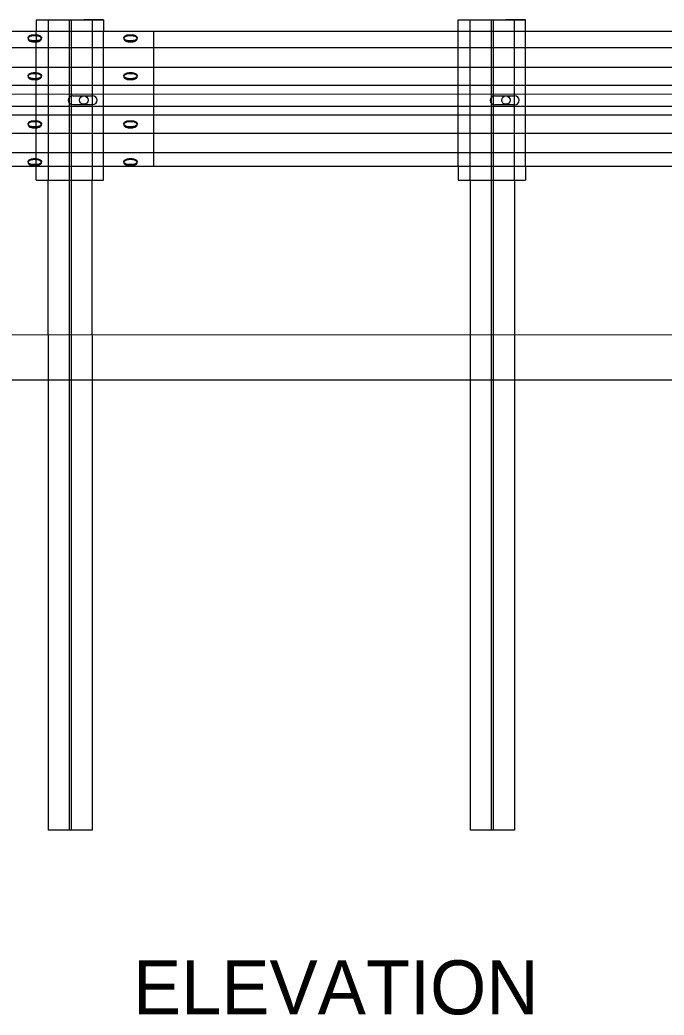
# Model space of a CAD drawing. Extents: x 49991 to 50160, y 49948 to 50051.
# Drawn here: x 50005.602 to 50006.556, y 49994.044 to 49995.518 of the extents above; entities that cross this region are included whole.
import ezdxf

# ---------------------------------------------------------------- set-up
doc = ezdxf.new("R2010")
doc.units = 0
for name, color, linetype in [('Level 1', 7, 'Continuous'), ('Level 2', 7, 'Continuous'), ('Level 4', 7, 'Continuous')]:
    doc.layers.add(name, color=color, linetype=linetype)

msp = doc.modelspace()

# ---------------------------------------------------------------- linework, layer by layer
at = {"layer": 'Level 1'}
for p, q in [((50005.6258, 49995.5184), (50005.7258, 49995.5184)), ((50005.6258, 49995.5184), (50005.6258, 49995.5019)), ((50005.6435, 49995.5184), (50005.7091, 49995.5184)), ((50005.7258, 49995.5184), (50005.6966, 49995.5184)), ((50005.7258, 49995.5184), (50005.7258, 49995.5019)), ((50006.2508, 49995.5184), (50006.3508, 49995.5184)), ((50006.2508, 49995.5019), (50006.2508, 49995.5184)), ((50006.2685, 49995.5184), (50006.3341, 49995.5184)), ((50006.3508, 49995.5184), (50006.3216, 49995.5184)), ((50006.3508, 49995.5018), (50006.3508, 49995.5184)), ((50004.3866, 49995.502), (50011.6716, 49995.5015)), ((50005.6219, 49995.4963), (50005.6258, 49995.4963)), ((50005.6219, 49995.4949), (50005.6219, 49995.4963)), ((50005.6258, 49995.4949), (50005.6219, 49995.4949)), ((50005.6258, 49995.4949), (50005.6258, 49995.4963)), ((50005.6258, 49995.4949), (50005.6258, 49995.4875)), ((50005.7636, 49995.4949), (50005.7636, 49995.4963)), ((50005.7636, 49995.4963), (50005.7675, 49995.4963)), ((50005.7675, 49995.4949), (50005.7636, 49995.4949)), ((50005.7675, 49995.4949), (50005.7675, 49995.4963)), ((50005.614, 49995.4919), (50005.614, 49995.4905)), ((50005.6258, 49995.4875), (50005.6219, 49995.4875)), ((50005.6219, 49995.4861), (50005.6219, 49995.4875)), ((50005.6219, 49995.4861), (50005.6258, 49995.4861)), ((50005.6258, 49995.4861), (50005.6258, 49995.4875)), ((50005.6337, 49995.4905), (50005.6337, 49995.4919)), ((50005.7675, 49995.4875), (50005.7636, 49995.4875)), ((50005.7636, 49995.4861), (50005.7636, 49995.4875)), ((50005.7636, 49995.4861), (50005.7675, 49995.4861)), ((50005.7675, 49995.4861), (50005.7675, 49995.4875)), ((50005.7754, 49995.4905), (50005.7754, 49995.4919)), ((50004.5497, 49995.4777), (50011.6716, 49995.4777)), ((50004.5497, 49995.4486), (50011.6716, 49995.448)), ((50005.614, 49995.4358), (50005.614, 49995.4344)), ((50005.6219, 49995.4403), (50005.6258, 49995.4403)), ((50005.6219, 49995.4403), (50005.6219, 49995.4388)), ((50005.6258, 49995.4388), (50005.6219, 49995.4388)), ((50005.6258, 49995.4403), (50005.6258, 49995.4388)), ((50005.6258, 49995.4314), (50005.6258, 49995.4388)), ((50005.6337, 49995.4344), (50005.6337, 49995.4358)), ((50005.7636, 49995.4403), (50005.7675, 49995.4403)), ((50005.7636, 49995.4403), (50005.7636, 49995.4388)), ((50005.7675, 49995.4388), (50005.7636, 49995.4388)), ((50005.7675, 49995.4403), (50005.7675, 49995.4388)), ((50005.7754, 49995.4344), (50005.7754, 49995.4358)), ((50004.5497, 49995.4215), (50011.6716, 49995.4225)), ((50005.6219, 49995.4314), (50005.6219, 49995.43)), ((50005.6258, 49995.4314), (50005.6219, 49995.4314)), ((50005.6219, 49995.43), (50005.6258, 49995.43)), ((50005.6258, 49995.4314), (50005.6258, 49995.43)), ((50005.7636, 49995.4314), (50005.7636, 49995.43)), ((50005.7675, 49995.4314), (50005.7636, 49995.4314)), ((50005.7636, 49995.43), (50005.7675, 49995.43)), ((50005.7675, 49995.4314), (50005.7675, 49995.43)), ((50005.0854, 49995.409), (50011.6716, 49995.4068)), ((50005.68, 49995.4061), (50005.7095, 49995.4061)), ((50006.3049, 49995.406), (50006.3345, 49995.406)), ((50011.6716, 49995.3902), (50005.5897, 49995.3903)), ((50005.7095, 49995.3929), (50005.68, 49995.3929)), ((50006.3345, 49995.3929), (50006.3049, 49995.3929)), ((50011.6716, 49995.3773), (50005.5897, 49995.3773)), ((50005.614, 49995.3646), (50005.614, 49995.3632)), ((50005.6219, 49995.369), (50005.6258, 49995.369)), ((50005.6219, 49995.3676), (50005.6219, 49995.369)), ((50005.6258, 49995.3676), (50005.6219, 49995.3676)), ((50005.6258, 49995.3676), (50005.6258, 49995.369)), ((50005.6258, 49995.3602), (50005.6258, 49995.3676)), ((50005.6337, 49995.3632), (50005.6337, 49995.3646)), ((50005.7636, 49995.369), (50005.7675, 49995.369)), ((50005.7636, 49995.3676), (50005.7636, 49995.369)), ((50005.7675, 49995.3676), (50005.7636, 49995.3676)), ((50005.7675, 49995.3676), (50005.7675, 49995.369)), ((50005.7754, 49995.3632), (50005.7754, 49995.3646)), ((50011.6716, 49995.3504), (50005.5897, 49995.3504)), ((50005.6258, 49995.3602), (50005.6219, 49995.3602)), ((50005.6219, 49995.3588), (50005.6219, 49995.3602)), ((50005.6219, 49995.3588), (50005.6258, 49995.3588)), ((50005.6258, 49995.3588), (50005.6258, 49995.3602)), ((50005.7675, 49995.3602), (50005.7636, 49995.3602)), ((50005.7636, 49995.3588), (50005.7636, 49995.3602)), ((50005.7636, 49995.3588), (50005.7675, 49995.3588)), ((50005.7675, 49995.3588), (50005.7675, 49995.3602)), ((50011.6716, 49995.3214), (50005.5897, 49995.3214)), ((50005.614, 49995.3085), (50005.614, 49995.3071)), ((50005.6219, 49995.313), (50005.6258, 49995.313)), ((50005.6219, 49995.313), (50005.6219, 49995.3115)), ((50005.6258, 49995.3115), (50005.6219, 49995.3115)), ((50005.6219, 49995.3041), (50005.6219, 49995.3027)), ((50005.6258, 49995.3041), (50005.6219, 49995.3041)), ((50005.6219, 49995.3027), (50005.6258, 49995.3027)), ((50005.6258, 49995.313), (50005.6258, 49995.3115)), ((50005.6258, 49995.3041), (50005.6258, 49995.3115)), ((50005.6258, 49995.3041), (50005.6258, 49995.3027)), ((50005.6337, 49995.3071), (50005.6337, 49995.3085)), ((50005.7636, 49995.313), (50005.7675, 49995.313)), ((50005.7636, 49995.313), (50005.7636, 49995.3115)), ((50005.7675, 49995.3115), (50005.7636, 49995.3115)), ((50005.7636, 49995.3041), (50005.7636, 49995.3027)), ((50005.7675, 49995.3041), (50005.7636, 49995.3041)), ((50005.7636, 49995.3027), (50005.7675, 49995.3027)), ((50005.7675, 49995.313), (50005.7675, 49995.3115)), ((50005.7675, 49995.3041), (50005.7675, 49995.3027)), ((50005.7754, 49995.3071), (50005.7754, 49995.3085)), ((50011.6716, 49995.3012), (50005.5897, 49995.3012)), ((50005.6258, 49995.2809), (50005.6258, 49995.3012)), ((50005.7258, 49995.2809), (50005.7258, 49995.3012)), ((50006.2508, 49995.3012), (50006.2508, 49995.2809)), ((50006.3508, 49995.3012), (50006.3508, 49995.2809)), ((50005.6258, 49995.2809), (50005.7258, 49995.2809)), ((50005.6435, 49995.0518), (50005.6435, 49995.2809)), ((50005.7091, 49995.0518), (50005.7091, 49995.2809)), ((50006.2508, 49995.2809), (50006.3508, 49995.2809)), ((50006.2685, 49995.2809), (50006.2685, 49995.0518)), ((50006.3341, 49995.2809), (50006.3341, 49995.0517)), ((50011.6716, 49995.0515), (50000.8175, 49995.052)), ((49999.8238, 49994.9854), (50011.6716, 49994.9849))]:
    msp.add_line(p, q, dxfattribs=at)
for points in [[(50005.6219, 49995.4875), (50005.6205, 49995.4876), (50005.6192, 49995.4878), (50005.6179, 49995.4881), (50005.6168, 49995.4885), (50005.6158, 49995.4891), (50005.6151, 49995.4897), (50005.6145, 49995.4904), (50005.6141, 49995.4912), (50005.614, 49995.4919), (50005.6141, 49995.4927), (50005.6145, 49995.4934), (50005.6151, 49995.4941), (50005.6158, 49995.4948), (50005.6168, 49995.4953), (50005.6179, 49995.4957), (50005.6192, 49995.4961), (50005.6205, 49995.4963), (50005.6219, 49995.4963)], [(50005.6219, 49995.4949), (50005.6205, 49995.4948), (50005.6192, 49995.4946), (50005.6179, 49995.4943), (50005.6168, 49995.4938), (50005.6158, 49995.4933), (50005.6151, 49995.4927), (50005.6145, 49995.492), (50005.6141, 49995.4912), (50005.6141, 49995.4912)], [(50005.6258, 49995.4963), (50005.6272, 49995.4963), (50005.6285, 49995.4961), (50005.6298, 49995.4957), (50005.6309, 49995.4953), (50005.6318, 49995.4948), (50005.6326, 49995.4941), (50005.6332, 49995.4934), (50005.6336, 49995.4927), (50005.6337, 49995.4919), (50005.6336, 49995.4912), (50005.6332, 49995.4904), (50005.6326, 49995.4897), (50005.6318, 49995.4891), (50005.6309, 49995.4885), (50005.6298, 49995.4881), (50005.6285, 49995.4878), (50005.6272, 49995.4876), (50005.6258, 49995.4875)], [(50005.6336, 49995.4912), (50005.6336, 49995.4912), (50005.6332, 49995.492), (50005.6326, 49995.4927), (50005.6318, 49995.4933), (50005.6309, 49995.4938), (50005.6298, 49995.4943), (50005.6285, 49995.4946), (50005.6272, 49995.4948), (50005.6258, 49995.4949)], [(50005.7636, 49995.4875), (50005.7622, 49995.4876), (50005.7609, 49995.4878), (50005.7597, 49995.4881), (50005.7586, 49995.4885), (50005.7576, 49995.4891), (50005.7568, 49995.4897), (50005.7562, 49995.4904), (50005.7559, 49995.4912), (50005.7557, 49995.4919), (50005.7559, 49995.4927), (50005.7562, 49995.4934), (50005.7568, 49995.4941), (50005.7576, 49995.4948), (50005.7586, 49995.4953), (50005.7597, 49995.4957), (50005.7609, 49995.4961), (50005.7622, 49995.4963), (50005.7636, 49995.4963)], [(50005.7636, 49995.4949), (50005.7622, 49995.4948), (50005.7609, 49995.4946), (50005.7597, 49995.4943), (50005.7586, 49995.4938), (50005.7576, 49995.4933), (50005.7568, 49995.4927), (50005.7562, 49995.492), (50005.7559, 49995.4912), (50005.7558, 49995.4912)], [(50005.7675, 49995.4963), (50005.7689, 49995.4963), (50005.7702, 49995.4961), (50005.7715, 49995.4957), (50005.7726, 49995.4953), (50005.7736, 49995.4948), (50005.7744, 49995.4941), (50005.7749, 49995.4934), (50005.7753, 49995.4927), (50005.7754, 49995.4919), (50005.7753, 49995.4912), (50005.7749, 49995.4904), (50005.7744, 49995.4897), (50005.7736, 49995.4891), (50005.7726, 49995.4885), (50005.7715, 49995.4881), (50005.7702, 49995.4878), (50005.7689, 49995.4876), (50005.7675, 49995.4875)], [(50005.7753, 49995.4912), (50005.7753, 49995.4912), (50005.7749, 49995.492), (50005.7744, 49995.4927), (50005.7736, 49995.4933), (50005.7726, 49995.4938), (50005.7715, 49995.4943), (50005.7702, 49995.4946), (50005.7689, 49995.4948), (50005.7675, 49995.4949)], [(50005.6141, 49995.4912), (50005.614, 49995.4905), (50005.6141, 49995.4897), (50005.6145, 49995.489), (50005.6151, 49995.4883), (50005.6158, 49995.4876), (50005.6168, 49995.4871), (50005.6179, 49995.4867), (50005.6192, 49995.4863), (50005.6205, 49995.4861), (50005.6219, 49995.4861)], [(50005.6258, 49995.4861), (50005.6272, 49995.4861), (50005.6285, 49995.4863), (50005.6298, 49995.4867), (50005.6309, 49995.4871), (50005.6318, 49995.4876), (50005.6326, 49995.4883), (50005.6332, 49995.489), (50005.6336, 49995.4897), (50005.6337, 49995.4905), (50005.6336, 49995.4912)], [(50005.7558, 49995.4912), (50005.7557, 49995.4905), (50005.7559, 49995.4897), (50005.7562, 49995.489), (50005.7568, 49995.4883), (50005.7576, 49995.4876), (50005.7586, 49995.4871), (50005.7597, 49995.4867), (50005.7609, 49995.4863), (50005.7622, 49995.4861), (50005.7636, 49995.4861)], [(50005.7675, 49995.4861), (50005.7689, 49995.4861), (50005.7702, 49995.4863), (50005.7715, 49995.4867), (50005.7726, 49995.4871), (50005.7736, 49995.4876), (50005.7744, 49995.4883), (50005.7749, 49995.489), (50005.7753, 49995.4897), (50005.7754, 49995.4905), (50005.7753, 49995.4912)], [(50005.6141, 49995.4351), (50005.614, 49995.4358), (50005.6141, 49995.4366), (50005.6145, 49995.4374), (50005.6151, 49995.438), (50005.6158, 49995.4387), (50005.6168, 49995.4392), (50005.6179, 49995.4397), (50005.6192, 49995.44), (50005.6205, 49995.4402), (50005.6219, 49995.4403)], [(50005.6219, 49995.4388), (50005.6205, 49995.4387), (50005.6192, 49995.4385), (50005.6179, 49995.4382), (50005.6168, 49995.4378), (50005.6158, 49995.4372), (50005.6151, 49995.4366), (50005.6145, 49995.4359), (50005.6141, 49995.4352), (50005.614, 49995.4344), (50005.6141, 49995.4336), (50005.6145, 49995.4329), (50005.6151, 49995.4322), (50005.6158, 49995.4316), (50005.6168, 49995.431), (50005.6179, 49995.4306), (50005.6192, 49995.4302), (50005.6205, 49995.43), (50005.6219, 49995.43)], [(50005.6219, 49995.4314), (50005.6205, 49995.4315), (50005.6192, 49995.4317), (50005.6179, 49995.432), (50005.6168, 49995.4325), (50005.6158, 49995.433), (50005.6151, 49995.4336), (50005.6145, 49995.4343), (50005.6141, 49995.4351), (50005.6141, 49995.4351)], [(50005.6258, 49995.4403), (50005.6272, 49995.4402), (50005.6285, 49995.44), (50005.6298, 49995.4397), (50005.6309, 49995.4392), (50005.6318, 49995.4387), (50005.6326, 49995.438), (50005.6332, 49995.4374), (50005.6336, 49995.4366), (50005.6337, 49995.4358), (50005.6336, 49995.4351)], [(50005.6258, 49995.43), (50005.6272, 49995.43), (50005.6285, 49995.4302), (50005.6298, 49995.4306), (50005.6309, 49995.431), (50005.6318, 49995.4316), (50005.6326, 49995.4322), (50005.6332, 49995.4329), (50005.6336, 49995.4336), (50005.6337, 49995.4344), (50005.6336, 49995.4352), (50005.6332, 49995.4359), (50005.6326, 49995.4366), (50005.6318, 49995.4372), (50005.6309, 49995.4378), (50005.6298, 49995.4382), (50005.6285, 49995.4385), (50005.6272, 49995.4387), (50005.6258, 49995.4388)], [(50005.6336, 49995.4351), (50005.6336, 49995.4351), (50005.6332, 49995.4343), (50005.6326, 49995.4336), (50005.6318, 49995.433), (50005.6309, 49995.4325), (50005.6298, 49995.432), (50005.6285, 49995.4317), (50005.6272, 49995.4315), (50005.6258, 49995.4314)], [(50005.7558, 49995.4351), (50005.7557, 49995.4358), (50005.7559, 49995.4366), (50005.7562, 49995.4374), (50005.7568, 49995.438), (50005.7576, 49995.4387), (50005.7586, 49995.4392), (50005.7597, 49995.4397), (50005.7609, 49995.44), (50005.7622, 49995.4402), (50005.7636, 49995.4403)], [(50005.7636, 49995.4388), (50005.7622, 49995.4387), (50005.7609, 49995.4385), (50005.7597, 49995.4382), (50005.7586, 49995.4378), (50005.7576, 49995.4372), (50005.7568, 49995.4366), (50005.7562, 49995.4359), (50005.7559, 49995.4352), (50005.7557, 49995.4344), (50005.7559, 49995.4336), (50005.7562, 49995.4329), (50005.7568, 49995.4322), (50005.7576, 49995.4316), (50005.7586, 49995.431), (50005.7597, 49995.4306), (50005.7609, 49995.4302), (50005.7622, 49995.43), (50005.7636, 49995.43)], [(50005.7636, 49995.4314), (50005.7622, 49995.4315), (50005.7609, 49995.4317), (50005.7597, 49995.432), (50005.7586, 49995.4325), (50005.7576, 49995.433), (50005.7568, 49995.4336), (50005.7562, 49995.4343), (50005.7559, 49995.4351), (50005.7558, 49995.4351)], [(50005.7675, 49995.4403), (50005.7689, 49995.4402), (50005.7702, 49995.44), (50005.7715, 49995.4397), (50005.7726, 49995.4392), (50005.7736, 49995.4387), (50005.7744, 49995.438), (50005.7749, 49995.4374), (50005.7753, 49995.4366), (50005.7754, 49995.4358), (50005.7753, 49995.4351)], [(50005.7675, 49995.43), (50005.7689, 49995.43), (50005.7702, 49995.4302), (50005.7715, 49995.4306), (50005.7726, 49995.431), (50005.7736, 49995.4316), (50005.7744, 49995.4322), (50005.7749, 49995.4329), (50005.7753, 49995.4336), (50005.7754, 49995.4344), (50005.7753, 49995.4352), (50005.7749, 49995.4359), (50005.7744, 49995.4366), (50005.7736, 49995.4372), (50005.7726, 49995.4378), (50005.7715, 49995.4382), (50005.7702, 49995.4385), (50005.7689, 49995.4387), (50005.7675, 49995.4388)], [(50005.7753, 49995.4351), (50005.7753, 49995.4351), (50005.7749, 49995.4343), (50005.7744, 49995.4336), (50005.7736, 49995.433), (50005.7726, 49995.4325), (50005.7715, 49995.432), (50005.7702, 49995.4317), (50005.7689, 49995.4315), (50005.7675, 49995.4314)], [(50005.6219, 49995.3602), (50005.6205, 49995.3603), (50005.6192, 49995.3605), (50005.6179, 49995.3608), (50005.6168, 49995.3612), (50005.6158, 49995.3618), (50005.6151, 49995.3624), (50005.6145, 49995.3631), (50005.6141, 49995.3639), (50005.614, 49995.3646), (50005.6141, 49995.3654), (50005.6145, 49995.3661), (50005.6151, 49995.3668), (50005.6158, 49995.3675), (50005.6168, 49995.368), (50005.6179, 49995.3684), (50005.6192, 49995.3688), (50005.6205, 49995.369), (50005.6219, 49995.369)], [(50005.6141, 49995.3639), (50005.614, 49995.3632), (50005.6141, 49995.3624), (50005.6145, 49995.3617), (50005.6151, 49995.361), (50005.6158, 49995.3603), (50005.6168, 49995.3598), (50005.6179, 49995.3594), (50005.6192, 49995.359), (50005.6205, 49995.3588), (50005.6219, 49995.3588)], [(50005.6219, 49995.3676), (50005.6205, 49995.3675), (50005.6192, 49995.3673), (50005.6179, 49995.367), (50005.6168, 49995.3666), (50005.6158, 49995.366), (50005.6151, 49995.3654), (50005.6145, 49995.3647), (50005.6141, 49995.3639), (50005.6141, 49995.3639)], [(50005.6258, 49995.369), (50005.6272, 49995.369), (50005.6285, 49995.3688), (50005.6298, 49995.3684), (50005.6309, 49995.368), (50005.6318, 49995.3675), (50005.6326, 49995.3668), (50005.6332, 49995.3661), (50005.6336, 49995.3654), (50005.6337, 49995.3646), (50005.6336, 49995.3639), (50005.6332, 49995.3631), (50005.6326, 49995.3624), (50005.6318, 49995.3618), (50005.6309, 49995.3612), (50005.6298, 49995.3608), (50005.6285, 49995.3605), (50005.6272, 49995.3603), (50005.6258, 49995.3602)], [(50005.6336, 49995.3639), (50005.6336, 49995.3639), (50005.6332, 49995.3647), (50005.6326, 49995.3654), (50005.6318, 49995.366), (50005.6309, 49995.3666), (50005.6298, 49995.367), (50005.6285, 49995.3673), (50005.6272, 49995.3675), (50005.6258, 49995.3676)], [(50005.6258, 49995.3588), (50005.6272, 49995.3588), (50005.6285, 49995.359), (50005.6298, 49995.3594), (50005.6309, 49995.3598), (50005.6318, 49995.3603), (50005.6326, 49995.361), (50005.6332, 49995.3617), (50005.6336, 49995.3624), (50005.6337, 49995.3632), (50005.6336, 49995.3639)], [(50005.7636, 49995.3602), (50005.7622, 49995.3603), (50005.7609, 49995.3605), (50005.7597, 49995.3608), (50005.7586, 49995.3612), (50005.7576, 49995.3618), (50005.7568, 49995.3624), (50005.7562, 49995.3631), (50005.7559, 49995.3639), (50005.7557, 49995.3646), (50005.7559, 49995.3654), (50005.7562, 49995.3661), (50005.7568, 49995.3668), (50005.7576, 49995.3675), (50005.7586, 49995.368), (50005.7597, 49995.3684), (50005.7609, 49995.3688), (50005.7622, 49995.369), (50005.7636, 49995.369)], [(50005.7558, 49995.3639), (50005.7557, 49995.3632), (50005.7559, 49995.3624), (50005.7562, 49995.3617), (50005.7568, 49995.361), (50005.7576, 49995.3603), (50005.7586, 49995.3598), (50005.7597, 49995.3594), (50005.7609, 49995.359), (50005.7622, 49995.3588), (50005.7636, 49995.3588)], [(50005.7636, 49995.3676), (50005.7622, 49995.3675), (50005.7609, 49995.3673), (50005.7597, 49995.367), (50005.7586, 49995.3666), (50005.7576, 49995.366), (50005.7568, 49995.3654), (50005.7562, 49995.3647), (50005.7559, 49995.3639), (50005.7558, 49995.3639)], [(50005.7675, 49995.369), (50005.7689, 49995.369), (50005.7702, 49995.3688), (50005.7715, 49995.3684), (50005.7726, 49995.368), (50005.7736, 49995.3675), (50005.7744, 49995.3668), (50005.7749, 49995.3661), (50005.7753, 49995.3654), (50005.7754, 49995.3646), (50005.7753, 49995.3639), (50005.7749, 49995.3631), (50005.7744, 49995.3624), (50005.7736, 49995.3618), (50005.7726, 49995.3612), (50005.7715, 49995.3608), (50005.7702, 49995.3605), (50005.7689, 49995.3603), (50005.7675, 49995.3602)], [(50005.7753, 49995.3639), (50005.7753, 49995.3639), (50005.7749, 49995.3647), (50005.7744, 49995.3654), (50005.7736, 49995.366), (50005.7726, 49995.3666), (50005.7715, 49995.367), (50005.7702, 49995.3673), (50005.7689, 49995.3675), (50005.7675, 49995.3676)], [(50005.7675, 49995.3588), (50005.7689, 49995.3588), (50005.7702, 49995.359), (50005.7715, 49995.3594), (50005.7726, 49995.3598), (50005.7736, 49995.3603), (50005.7744, 49995.361), (50005.7749, 49995.3617), (50005.7753, 49995.3624), (50005.7754, 49995.3632), (50005.7753, 49995.3639)], [(50005.6141, 49995.3078), (50005.614, 49995.3085), (50005.6141, 49995.3093), (50005.6145, 49995.3101), (50005.6151, 49995.3107), (50005.6158, 49995.3114), (50005.6168, 49995.3119), (50005.6179, 49995.3124), (50005.6192, 49995.3127), (50005.6205, 49995.3129), (50005.6219, 49995.313)], [(50005.6219, 49995.3115), (50005.6205, 49995.3114), (50005.6192, 49995.3112), (50005.6179, 49995.3109), (50005.6168, 49995.3105), (50005.6158, 49995.3099), (50005.6151, 49995.3093), (50005.6145, 49995.3086), (50005.6141, 49995.3079), (50005.614, 49995.3071), (50005.6141, 49995.3063), (50005.6145, 49995.3056), (50005.6151, 49995.3049), (50005.6158, 49995.3043), (50005.6168, 49995.3037), (50005.6179, 49995.3033), (50005.6192, 49995.303), (50005.6205, 49995.3028), (50005.6219, 49995.3027)], [(50005.6219, 49995.3041), (50005.6205, 49995.3042), (50005.6192, 49995.3044), (50005.6179, 49995.3047), (50005.6168, 49995.3052), (50005.6158, 49995.3057), (50005.6151, 49995.3063), (50005.6145, 49995.307), (50005.6141, 49995.3078), (50005.6141, 49995.3078)], [(50005.6258, 49995.313), (50005.6272, 49995.3129), (50005.6285, 49995.3127), (50005.6298, 49995.3124), (50005.6309, 49995.3119), (50005.6318, 49995.3114), (50005.6326, 49995.3107), (50005.6332, 49995.3101), (50005.6336, 49995.3093), (50005.6337, 49995.3085), (50005.6336, 49995.3078)], [(50005.6258, 49995.3027), (50005.6272, 49995.3028), (50005.6285, 49995.303), (50005.6298, 49995.3033), (50005.6309, 49995.3037), (50005.6318, 49995.3043), (50005.6326, 49995.3049), (50005.6332, 49995.3056), (50005.6336, 49995.3063), (50005.6337, 49995.3071), (50005.6336, 49995.3079), (50005.6332, 49995.3086), (50005.6326, 49995.3093), (50005.6318, 49995.3099), (50005.6309, 49995.3105), (50005.6298, 49995.3109), (50005.6285, 49995.3112), (50005.6272, 49995.3114), (50005.6258, 49995.3115)], [(50005.6336, 49995.3078), (50005.6336, 49995.3078), (50005.6332, 49995.307), (50005.6326, 49995.3063), (50005.6318, 49995.3057), (50005.6309, 49995.3052), (50005.6298, 49995.3047), (50005.6285, 49995.3044), (50005.6272, 49995.3042), (50005.6258, 49995.3041)], [(50005.7558, 49995.3078), (50005.7557, 49995.3085), (50005.7559, 49995.3093), (50005.7562, 49995.3101), (50005.7568, 49995.3107), (50005.7576, 49995.3114), (50005.7586, 49995.3119), (50005.7597, 49995.3124), (50005.7609, 49995.3127), (50005.7622, 49995.3129), (50005.7636, 49995.313)], [(50005.7636, 49995.3115), (50005.7622, 49995.3114), (50005.7609, 49995.3112), (50005.7597, 49995.3109), (50005.7586, 49995.3105), (50005.7576, 49995.3099), (50005.7568, 49995.3093), (50005.7562, 49995.3086), (50005.7559, 49995.3079), (50005.7557, 49995.3071), (50005.7559, 49995.3063), (50005.7562, 49995.3056), (50005.7568, 49995.3049), (50005.7576, 49995.3043), (50005.7586, 49995.3037), (50005.7597, 49995.3033), (50005.7609, 49995.303), (50005.7622, 49995.3028), (50005.7636, 49995.3027)], [(50005.7636, 49995.3041), (50005.7622, 49995.3042), (50005.7609, 49995.3044), (50005.7597, 49995.3047), (50005.7586, 49995.3052), (50005.7576, 49995.3057), (50005.7568, 49995.3063), (50005.7562, 49995.307), (50005.7559, 49995.3078), (50005.7558, 49995.3078)], [(50005.7675, 49995.313), (50005.7689, 49995.3129), (50005.7702, 49995.3127), (50005.7715, 49995.3124), (50005.7726, 49995.3119), (50005.7736, 49995.3114), (50005.7744, 49995.3107), (50005.7749, 49995.3101), (50005.7753, 49995.3093), (50005.7754, 49995.3085), (50005.7753, 49995.3078)], [(50005.7675, 49995.3027), (50005.7689, 49995.3028), (50005.7702, 49995.303), (50005.7715, 49995.3033), (50005.7726, 49995.3037), (50005.7736, 49995.3043), (50005.7744, 49995.3049), (50005.7749, 49995.3056), (50005.7753, 49995.3063), (50005.7754, 49995.3071), (50005.7753, 49995.3079), (50005.7749, 49995.3086), (50005.7744, 49995.3093), (50005.7736, 49995.3099), (50005.7726, 49995.3105), (50005.7715, 49995.3109), (50005.7702, 49995.3112), (50005.7689, 49995.3114), (50005.7675, 49995.3115)], [(50005.7753, 49995.3078), (50005.7753, 49995.3078), (50005.7749, 49995.307), (50005.7744, 49995.3063), (50005.7736, 49995.3057), (50005.7726, 49995.3052), (50005.7715, 49995.3047), (50005.7702, 49995.3044), (50005.7689, 49995.3042), (50005.7675, 49995.3041)]]:
    msp.add_lwpolyline(points, dxfattribs=at)
for centre in [(50005.6966, 49995.3997), (50006.3216, 49995.3997)]:
    msp.add_circle(centre, 0.00625, dxfattribs=at)
for centre, start, end in [((50005.68, 49995.3995), 90, 270), ((50005.7095, 49995.3995), 270, 90), ((50006.3049, 49995.3994), 90, 270), ((50006.3345, 49995.3994), 270, 90)]:
    msp.add_arc(centre, 0.00656, start, end, dxfattribs=at)
at = {"layer": 'Level 4'}
for p, q in [((50005.6435, 49995.5184), (50005.6435, 49995.2809)), ((50005.6749, 49995.5184), (50005.6749, 49994.3184)), ((50005.6777, 49995.5184), (50005.6777, 49994.3184)), ((50005.7091, 49995.5184), (50005.7091, 49995.2809)), ((50006.2685, 49995.2809), (50006.2685, 49995.5184)), ((50006.2999, 49995.5184), (50006.2999, 49994.3184)), ((50006.3027, 49995.5184), (50006.3027, 49994.3184)), ((50006.3341, 49995.2809), (50006.3341, 49995.5184)), ((50005.6258, 49995.4963), (50005.6258, 49995.5019)), ((50005.7258, 49995.3012), (50005.7258, 49995.5019)), ((50005.7997, 49995.5019), (50005.7997, 49995.4989)), ((50005.7997, 49995.4989), (50005.7997, 49995.4978)), ((50005.7997, 49995.4978), (50005.7997, 49995.4777)), ((50006.2508, 49995.3012), (50006.2508, 49995.5019)), ((50006.3508, 49995.3012), (50006.3508, 49995.5018)), ((50005.6258, 49995.4403), (50005.6258, 49995.4861)), ((50005.7997, 49995.4777), (50005.7997, 49995.4487)), ((50005.7997, 49995.4487), (50005.7997, 49995.4217)), ((50005.6258, 49995.369), (50005.6258, 49995.43)), ((50005.7997, 49995.4217), (50005.7997, 49995.4087)), ((50005.7997, 49995.4087), (50005.7997, 49995.3903)), ((50005.7997, 49995.3903), (50005.7997, 49995.3773)), ((50005.7997, 49995.3773), (50005.7997, 49995.3504)), ((50005.6258, 49995.313), (50005.6258, 49995.3588)), ((50005.7997, 49995.3504), (50005.7997, 49995.3214)), ((50005.7997, 49995.3214), (50005.7997, 49995.3012)), ((50005.6258, 49995.3012), (50005.6258, 49995.3027)), ((50005.6435, 49995.0518), (50005.6435, 49994.3184)), ((50005.7091, 49995.0518), (50005.7091, 49994.3184)), ((50006.2685, 49995.0518), (50006.2685, 49994.3184)), ((50006.3341, 49995.0517), (50006.3341, 49994.3184)), ((50005.7091, 49994.3184), (50005.6435, 49994.3184)), ((50006.3341, 49994.3184), (50006.2685, 49994.3184))]:
    msp.add_line(p, q, dxfattribs=at)

# ---------------------------------------------------------------- texts
at = {"layer": 'Level 2'}
msp.add_text('ELEVATION', height=0.08, dxfattribs=at).set_placement((50005.7693, 49994.0455))

doc.saveas('drawing.dxf')
